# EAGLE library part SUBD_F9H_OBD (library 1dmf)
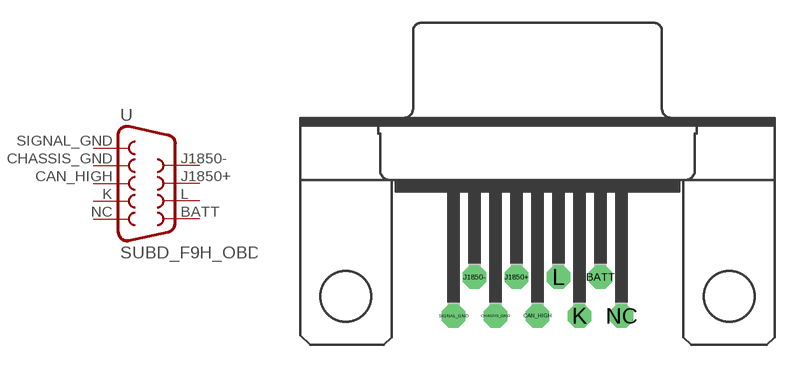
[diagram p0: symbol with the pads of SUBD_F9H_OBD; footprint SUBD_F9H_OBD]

Designator prefix -

## SUBD_F9H_OBD1  [SUBD_F9H_OBD]
BATT  9  pas
CAN_HIGH  3  pas
CHASSIS_GND  2  pas
J1850+  7  pas
J1850-  6  pas
K  4  pas
L  8  pas
NC  5  pas
SIGNAL_GND  1  pas

## Footprint SUBD_F9H_OBD (pad centres in mm)
drill 1.016 octagon: BATT 2.845,-5.08; CAN_HIGH -1.27,-7.62; CHASSIS_GND -4.013,-7.62; J1850+ -2.642,-5.08; J1850- -5.385,-5.08; K 1.473,-7.62; L 0.102,-5.08; NC 4.216,-7.62; SIGNAL_GND -6.756,-7.62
